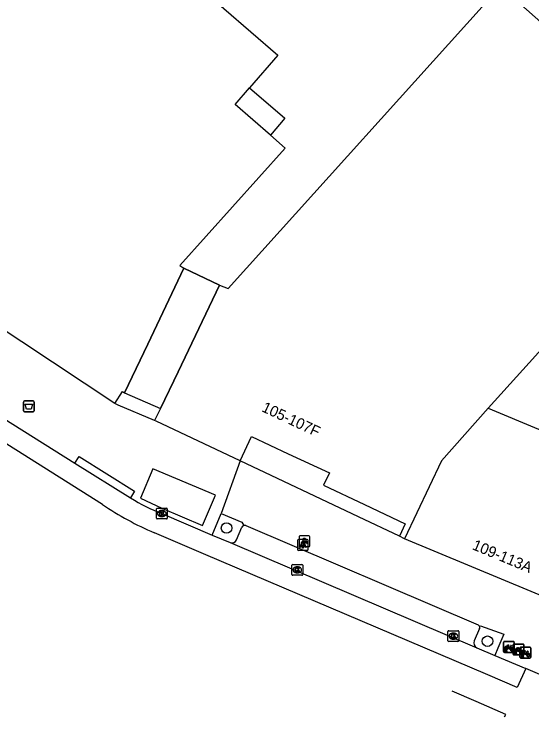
# Model space of a CAD drawing. Extents: x 161771 to 163125, y 382479 to 383177.
# Drawn here: x 162145.8 to 162193.7, y 382638.5 to 382703.5 of the extents above; entities that cross this region are included whole.
import ezdxf

# ---------------------------------------------------------------- set-up
doc = ezdxf.new("R2010")
doc.units = 0
for name, color, linetype in [('IMGEO_Afvalbak', 7, 'Continuous'), ('IMGEO_Boom', 7, 'Continuous'), ('IMGEO_Fietsenrek', 7, 'Continuous'), ('IMGEO_Kolk', 7, 'Continuous'), ('IMGEO_Lichtpunt', 7, 'Continuous'), ('IMGEO_Pand', 7, 'Continuous'), ('IMGEO_Pand_nummerreeks', 7, 'Continuous'), ('IMGEO_Pand_overbouw', 7, 'Continuous'), ('IMGEO_Parkeervlak_open', 7, 'Continuous'), ('IMGEO_Rijbaan_lokaal_gesloten', 7, 'Continuous'), ('IMGEO_Rijbaan_lokaal_open', 7, 'Continuous'), ('IMGEO_Voetpad_open', 7, 'Continuous')]:
    doc.layers.add(name, color=color, linetype=linetype)

msp = doc.modelspace()

# ---------------------------------------------------------------- linework, layer by layer
at = {"layer": 'IMGEO_Afvalbak'}
for p, q in [((162146.704, 382666.789), (162146.704, 382667.589)), ((162146.704, 382667.589), (162146.704, 382666.789)), ((162146.804, 382667.689), (162147.594, 382667.689)), ((162147.594, 382667.689), (162146.804, 382667.689)), ((162147.694, 382667.589), (162147.694, 382666.789)), ((162147.694, 382666.789), (162147.694, 382667.589)), ((162147.594, 382666.689), (162146.804, 382666.689)), ((162146.804, 382666.689), (162147.594, 382666.689))]:
    msp.add_line(p, q, dxfattribs=at)
msp.add_lwpolyline([(162146.847, 382667.403), (162147.551, 382667.403), (162147.402, 382666.933), (162146.996, 382666.933), (162146.847, 382667.403)], dxfattribs=at)
for centre, start, end in [((162146.804, 382667.589), 90, 180), ((162146.804, 382667.589), 90, 180), ((162147.594, 382667.589), 0, 90), ((162147.594, 382667.589), 360, 90), ((162146.804, 382666.789), 180, 270), ((162146.804, 382666.789), 180, 270), ((162147.594, 382666.789), 270, 0), ((162147.594, 382666.789), 270, 0)]:
    msp.add_arc(centre, 0.1, start, end, dxfattribs=at)
at = {"layer": 'IMGEO_Boom'}
for centre in [(162165.482, 382655.944), (162189.61, 382645.483)]:
    msp.add_circle(centre, 0.489, dxfattribs=at)
at = {"layer": 'IMGEO_Fietsenrek'}
for p, q in [((162191.09, 382644.528), (162191.09, 382645.369)), ((162191.09, 382645.369), (162191.09, 382644.528)), ((162191.165, 382645.453), (162192.006, 382645.453)), ((162192.006, 382645.453), (162191.165, 382645.453)), ((162192.052, 382645.218), (162192.893, 382645.218)), ((162192.893, 382645.218), (162192.052, 382645.218)), ((162192.09, 382645.378), (162192.09, 382644.537)), ((162192.09, 382644.537), (162192.09, 382645.378)), ((162191.217, 382644.537), (162191.256, 382644.697)), ((162191.251, 382644.537), (162191.217, 382644.537)), ((162191.286, 382644.685), (162191.251, 382644.537)), ((162191.328, 382644.709), (162191.327, 382644.713)), ((162191.369, 382644.537), (162191.335, 382644.679)), ((162191.359, 382644.72), (162191.36, 382644.713)), ((162191.367, 382644.683), (162191.402, 382644.537)), ((162191.402, 382644.537), (162191.369, 382644.537)), ((162191.777, 382645.002), (162191.813, 382644.907)), ((162191.977, 382644.293), (162191.977, 382645.134)), ((162191.977, 382645.134), (162191.977, 382644.293)), ((162192.613, 382644.004), (162192.613, 382644.845)), ((162192.613, 382644.845), (162192.613, 382644.004)), ((162192.664, 382644.767), (162192.7, 382644.672)), ((162192.688, 382644.929), (162193.529, 382644.929)), ((162193.529, 382644.929), (162192.688, 382644.929)), ((162192.977, 382645.143), (162192.977, 382644.302)), ((162192.977, 382644.302), (162192.977, 382645.143)), ((162193.613, 382644.854), (162193.613, 382644.013)), ((162193.613, 382644.013), (162193.613, 382644.854)), ((162192.015, 382644.453), (162191.174, 382644.453)), ((162191.174, 382644.453), (162192.015, 382644.453)), ((162192.902, 382644.218), (162192.061, 382644.218)), ((162192.061, 382644.218), (162192.902, 382644.218)), ((162192.104, 382644.302), (162192.143, 382644.462)), ((162192.138, 382644.302), (162192.104, 382644.302)), ((162192.173, 382644.45), (162192.138, 382644.302)), ((162192.215, 382644.474), (162192.214, 382644.478)), ((162192.256, 382644.302), (162192.222, 382644.444)), ((162192.246, 382644.485), (162192.247, 382644.478)), ((162192.254, 382644.448), (162192.289, 382644.302)), ((162192.289, 382644.302), (162192.256, 382644.302)), ((162193.538, 382643.929), (162192.697, 382643.929)), ((162192.697, 382643.929), (162193.538, 382643.929)), ((162192.74, 382644.013), (162192.779, 382644.173)), ((162192.774, 382644.013), (162192.74, 382644.013)), ((162192.809, 382644.161), (162192.774, 382644.013)), ((162192.851, 382644.185), (162192.85, 382644.189)), ((162192.892, 382644.013), (162192.858, 382644.155)), ((162192.882, 382644.196), (162192.883, 382644.189)), ((162192.89, 382644.159), (162192.925, 382644.013)), ((162192.925, 382644.013), (162192.892, 382644.013)), ((162193.3, 382644.478), (162193.336, 382644.383))]:
    msp.add_line(p, q, dxfattribs=at)
for points in [[(162191.424, 382644.927), (162191.372, 382644.837), (162191.332, 382644.812), (162191.333, 382644.859), (162191.388, 382644.953)], [(162191.403, 382644.979), (162191.498, 382645.143), (162191.584, 382645.129), (162191.586, 382645.12), (162191.53, 382645.109), (162191.503, 382645.064), (162191.759, 382645.023)], [(162191.699, 382644.735), (162191.649, 382644.735), (162191.458, 382644.986), (162191.439, 382644.954)], [(162191.746, 382644.998), (162191.489, 382645.039), (162191.472, 382645.01), (162191.639, 382644.79), (162191.746, 382644.998)], [(162191.794, 382644.9), (162191.764, 382644.977), (162191.655, 382644.759), (162191.698, 382644.759)], [(162191.728, 382644.759), (162191.848, 382644.758), (162191.804, 382644.872)], [(162191.824, 382644.879), (162191.879, 382644.734), (162191.729, 382644.734)], [(162191.759, 382645.023), (162191.784, 382645.072), (162191.778, 382645.076), (162191.755, 382645.08), (162191.743, 382645.087), (162191.742, 382645.09), (162191.744, 382645.095), (162191.839, 382645.08), (162191.841, 382645.07), (162191.831, 382645.057), (162191.819, 382645.051), (162191.805, 382645.057), (162191.777, 382645.002)], [(162192.311, 382644.692), (162192.259, 382644.602), (162192.219, 382644.577), (162192.22, 382644.624), (162192.275, 382644.718)], [(162192.29, 382644.744), (162192.385, 382644.908), (162192.471, 382644.894), (162192.473, 382644.885), (162192.417, 382644.874), (162192.39, 382644.829), (162192.646, 382644.788)], [(162192.586, 382644.5), (162192.536, 382644.5), (162192.345, 382644.751), (162192.326, 382644.719)], [(162192.633, 382644.763), (162192.376, 382644.804), (162192.359, 382644.775), (162192.526, 382644.555), (162192.633, 382644.763)], [(162192.681, 382644.665), (162192.651, 382644.742), (162192.542, 382644.524), (162192.585, 382644.524)], [(162192.615, 382644.524), (162192.735, 382644.523), (162192.691, 382644.637)], [(162192.711, 382644.644), (162192.766, 382644.499), (162192.616, 382644.499)], [(162192.646, 382644.788), (162192.671, 382644.837), (162192.665, 382644.841), (162192.642, 382644.845), (162192.63, 382644.852), (162192.629, 382644.855), (162192.631, 382644.86), (162192.726, 382644.845), (162192.728, 382644.835), (162192.718, 382644.822), (162192.706, 382644.816), (162192.692, 382644.822), (162192.664, 382644.767)], [(162192.926, 382644.455), (162193.021, 382644.619), (162193.107, 382644.605), (162193.109, 382644.596), (162193.053, 382644.585), (162193.026, 382644.54), (162193.282, 382644.499)], [(162193.269, 382644.474), (162193.012, 382644.515), (162192.995, 382644.486), (162193.162, 382644.266), (162193.269, 382644.474)], [(162193.282, 382644.499), (162193.307, 382644.548), (162193.301, 382644.552), (162193.278, 382644.556), (162193.266, 382644.563), (162193.265, 382644.566), (162193.267, 382644.571), (162193.362, 382644.556), (162193.364, 382644.546), (162193.354, 382644.533), (162193.342, 382644.527), (162193.328, 382644.533), (162193.3, 382644.478)], [(162192.947, 382644.403), (162192.895, 382644.313), (162192.855, 382644.288), (162192.856, 382644.335), (162192.911, 382644.429)], [(162193.222, 382644.211), (162193.172, 382644.211), (162192.981, 382644.462), (162192.962, 382644.43)], [(162193.317, 382644.376), (162193.287, 382644.453), (162193.178, 382644.235), (162193.221, 382644.235)], [(162193.251, 382644.235), (162193.371, 382644.234), (162193.327, 382644.348)], [(162193.347, 382644.355), (162193.402, 382644.21), (162193.252, 382644.21)]]:
    msp.add_lwpolyline(points, dxfattribs=at)
for centre, radius, start, end in [((162191.168, 382645.375), 0.0779, 92.4484, 184.28452), ((162191.168, 382645.375), 0.0779, 92.4484, 184.28452), ((162192.055, 382645.14), 0.0779, 92.4484, 184.28452), ((162192.055, 382645.14), 0.0779, 92.4484, 184.28452), ((162192.012, 382645.375), 0.0779, 2.4484, 94.28452), ((162192.012, 382645.375), 0.0779, 2.4484, 94.28452), ((162192.899, 382645.14), 0.0779, 2.4484, 94.28452), ((162192.899, 382645.14), 0.0779, 2.4484, 94.28452), ((162191.168, 382644.531), 0.0779, 182.4484, 274.28452), ((162191.168, 382644.531), 0.0779, 182.4484, 274.28452), ((162191.33, 382644.838), 0.159, 62.67661, 242.13685), ((162191.33, 382644.838), 0.129, 63.31916, 238.90302), ((162191.31, 382644.709), 0.0499, 12.8025, 158.69338), ((162191.33, 382644.838), 0.159, 253.99666, 271.78671), ((162191.31, 382644.709), 0.0174, 12.8025, 163.45023), ((162191.33, 382644.838), 0.129, 253.41502, 269.02044), ((162191.33, 382644.838), 0.129, 283.60429, 43.43025), ((162191.33, 382644.838), 0.159, 283.5766, 46.60424), ((162191.857, 382644.754), 0.159, 113.3408, 178.32165), ((162191.857, 382644.754), 0.159, 187.0065, 105.77075), ((162191.857, 382644.754), 0.129, 113.92302, 177.95563), ((162191.857, 382644.754), 0.129, 188.67146, 104.58832), ((162192.012, 382644.531), 0.0779, 272.4484, 4.28452), ((162192.012, 382644.531), 0.0779, 272.4484, 4.28452), ((162192.217, 382644.603), 0.159, 62.67661, 242.13685), ((162192.217, 382644.603), 0.129, 63.31916, 238.90302), ((162192.197, 382644.474), 0.0499, 12.8025, 158.69338), ((162192.217, 382644.603), 0.129, 283.60429, 43.43025), ((162192.217, 382644.603), 0.159, 283.5766, 46.60424), ((162192.744, 382644.519), 0.159, 113.3408, 178.32165), ((162192.744, 382644.519), 0.159, 187.0065, 105.77075), ((162192.691, 382644.851), 0.0779, 92.4484, 184.28452), ((162192.691, 382644.851), 0.0779, 92.4484, 184.28452), ((162192.744, 382644.519), 0.129, 113.92302, 177.95563), ((162192.744, 382644.519), 0.129, 188.67146, 104.58832), ((162193.535, 382644.851), 0.0779, 2.4484, 94.28452), ((162193.535, 382644.851), 0.0779, 2.4484, 94.28452), ((162192.055, 382644.296), 0.0779, 182.4484, 274.28452), ((162192.055, 382644.296), 0.0779, 182.4484, 274.28452), ((162192.217, 382644.603), 0.159, 253.99666, 271.78671), ((162192.197, 382644.474), 0.0174, 12.8025, 163.45023), ((162192.217, 382644.603), 0.129, 253.41502, 269.02044), ((162192.691, 382644.007), 0.0779, 182.4484, 274.28452), ((162192.691, 382644.007), 0.0779, 182.4484, 274.28452), ((162192.853, 382644.314), 0.159, 62.67661, 242.13685), ((162192.853, 382644.314), 0.129, 63.31916, 238.90302), ((162192.833, 382644.185), 0.0499, 12.8025, 158.69338), ((162192.853, 382644.314), 0.159, 253.99666, 271.78671), ((162192.833, 382644.185), 0.0174, 12.8025, 163.45023), ((162192.853, 382644.314), 0.129, 253.41502, 269.02044), ((162192.853, 382644.314), 0.129, 283.60429, 43.43025), ((162192.853, 382644.314), 0.159, 283.5766, 46.60424), ((162192.899, 382644.296), 0.0779, 272.4484, 4.28452), ((162192.899, 382644.296), 0.0779, 272.4484, 4.28452), ((162193.38, 382644.23), 0.159, 113.3408, 178.32165), ((162193.38, 382644.23), 0.159, 187.0065, 105.77075), ((162193.38, 382644.23), 0.129, 113.92302, 177.95563), ((162193.38, 382644.23), 0.129, 188.67146, 104.58832), ((162193.535, 382644.007), 0.0779, 272.4484, 4.28452), ((162193.535, 382644.007), 0.0779, 272.4484, 4.28452)]:
    msp.add_arc(centre, radius, start, end, dxfattribs=at)
at = {"layer": 'IMGEO_Kolk'}
for p, q in [((162158.997, 382656.858), (162158.997, 382657.71)), ((162159.072, 382657.784), (162159.924, 382657.784)), ((162159.485, 382657.564), (162159.51, 382657.564)), ((162159.998, 382657.71), (162159.998, 382656.858)), ((162159.508, 382657.004), (162159.483, 382657.004)), ((162159.924, 382656.784), (162159.072, 382656.784)), ((162171.523, 382651.653), (162171.523, 382652.505)), ((162171.598, 382652.579), (162172.45, 382652.579)), ((162172.011, 382652.359), (162172.036, 382652.359)), ((162172.524, 382652.505), (162172.524, 382651.653)), ((162172.034, 382651.799), (162172.009, 382651.799)), ((162172.45, 382651.579), (162171.598, 382651.579)), ((162186.026, 382646.452), (162186.878, 382646.452)), ((162185.951, 382645.526), (162185.951, 382646.378)), ((162186.439, 382646.232), (162186.464, 382646.232)), ((162186.952, 382646.378), (162186.952, 382645.526)), ((162186.878, 382645.452), (162186.026, 382645.452)), ((162186.462, 382645.672), (162186.437, 382645.672))]:
    msp.add_line(p, q, dxfattribs=at)
for points in [[(162158.997, 382656.858), (162158.997, 382657.71)], [(162159.072, 382657.784), (162159.924, 382657.784)], [(162159.998, 382657.71), (162159.998, 382656.858)], [(162159.318, 382657.484), (162159.441, 382657.484), (162159.441, 382657.333), (162159.571, 382657.484), (162159.735, 382657.484), (162159.589, 382657.333), (162159.742, 382657.084), (162159.59, 382657.084), (162159.505, 382657.248), (162159.441, 382657.181), (162159.441, 382657.084), (162159.318, 382657.084), (162159.318, 382657.484)], [(162159.924, 382656.784), (162159.072, 382656.784)], [(162171.523, 382651.653), (162171.523, 382652.505)], [(162171.598, 382652.579), (162172.45, 382652.579)], [(162172.524, 382652.505), (162172.524, 382651.653)], [(162171.844, 382652.279), (162171.967, 382652.279), (162171.967, 382652.128), (162172.097, 382652.279), (162172.261, 382652.279), (162172.115, 382652.128), (162172.268, 382651.879), (162172.116, 382651.879), (162172.031, 382652.043), (162171.967, 382651.976), (162171.967, 382651.879), (162171.844, 382651.879), (162171.844, 382652.279)], [(162172.45, 382651.579), (162171.598, 382651.579)], [(162186.026, 382646.452), (162186.878, 382646.452)], [(162185.951, 382645.526), (162185.951, 382646.378)], [(162186.272, 382646.152), (162186.395, 382646.152), (162186.395, 382646.001), (162186.525, 382646.152), (162186.689, 382646.152), (162186.543, 382646.001), (162186.696, 382645.752), (162186.544, 382645.752), (162186.459, 382645.916), (162186.395, 382645.849), (162186.395, 382645.752), (162186.272, 382645.752), (162186.272, 382646.152)], [(162186.952, 382646.378), (162186.952, 382645.526)], [(162186.878, 382645.452), (162186.026, 382645.452)]]:
    msp.add_lwpolyline(points, dxfattribs=at)
for centre, start, end in [((162159.074, 382657.708), 91.55205, 178.44795), ((162159.074, 382657.708), 91.55205, 178.44795), ((162159.922, 382657.708), 1.55205, 88.44795), ((162159.922, 382657.708), 1.55205, 88.44795), ((162159.074, 382656.86), 181.55205, 268.44795), ((162159.074, 382656.86), 181.55205, 268.44795), ((162159.922, 382656.86), 271.55205, 358.44795), ((162159.922, 382656.86), 271.55205, 358.44795), ((162171.6, 382652.503), 91.55205, 178.44795), ((162171.6, 382652.503), 91.55205, 178.44795), ((162172.448, 382652.503), 1.55205, 88.44795), ((162172.448, 382652.503), 1.55205, 88.44795), ((162171.6, 382651.655), 181.55205, 268.44795), ((162171.6, 382651.655), 181.55205, 268.44795), ((162172.448, 382651.655), 271.55205, 358.44795), ((162172.448, 382651.655), 271.55205, 358.44795), ((162186.028, 382646.376), 91.55205, 178.44795), ((162186.028, 382646.376), 91.55205, 178.44795), ((162186.876, 382646.376), 1.55205, 88.44795), ((162186.876, 382646.376), 1.55205, 88.44795), ((162186.028, 382645.528), 181.55205, 268.44795), ((162186.028, 382645.528), 181.55205, 268.44795), ((162186.876, 382645.528), 271.55205, 358.44795), ((162186.876, 382645.528), 271.55205, 358.44795)]:
    msp.add_arc(centre, 0.0765, start, end, dxfattribs=at)
for centre, major_axis, ratio, start_param, end_param in [((162159.484, 382657.284), (-0.387, 0.002), 0.722429, 4.712389, 7.853982), ((162159.509, 382657.284), (-0.39, 0.002), 0.717154, 1.570796, 4.712389), ((162172.01, 382652.079), (-0.387, 0.002), 0.722429, 4.712389, 7.853982), ((162172.035, 382652.079), (-0.39, 0.002), 0.717154, 1.570796, 4.712389), ((162186.438, 382645.952), (-0.387, 0.002), 0.722429, 4.712389, 7.853982), ((162186.463, 382645.952), (-0.39, 0.002), 0.717154, 1.570796, 4.712389)]:
    msp.add_ellipse(centre, major_axis=major_axis, ratio=ratio, start_param=start_param, end_param=end_param, dxfattribs=at)
at = {"layer": 'IMGEO_Lichtpunt'}
for p, q in [((162172.183, 382655.125), (162172.183, 382654.318)), ((162172.183, 382655.125), (162172.183, 382654.318)), ((162173.085, 382655.22), (162172.277, 382655.22)), ((162173.085, 382655.22), (162172.277, 382655.22)), ((162173.179, 382654.318), (162173.179, 382655.125)), ((162173.179, 382654.318), (162173.179, 382655.125)), ((162172.04, 382654.785), (162172.04, 382653.978)), ((162172.04, 382654.785), (162172.04, 382653.978)), ((162172.942, 382654.88), (162172.134, 382654.88)), ((162172.942, 382654.88), (162172.134, 382654.88)), ((162173.036, 382653.978), (162173.036, 382654.785)), ((162173.036, 382653.978), (162173.036, 382654.785)), ((162172.134, 382653.884), (162172.942, 382653.884)), ((162172.134, 382653.884), (162172.942, 382653.884)), ((162172.277, 382654.224), (162173.085, 382654.224)), ((162172.277, 382654.224), (162173.085, 382654.224))]:
    msp.add_line(p, q, dxfattribs=at)
for points in [[(162172.414, 382654.449), (162172.453, 382654.421), (162172.265, 382654.159), (162172.227, 382654.186), (162172.414, 382654.449)], [(162172.557, 382654.789), (162172.596, 382654.761), (162172.408, 382654.499), (162172.37, 382654.526), (162172.557, 382654.789)], [(162172.516, 382654.401), (162172.563, 382654.401), (162172.563, 382654.079), (162172.516, 382654.079), (162172.516, 382654.401)], [(162172.626, 382654.421), (162172.664, 382654.448), (162172.851, 382654.186), (162172.812, 382654.158), (162172.626, 382654.421)], [(162172.659, 382654.741), (162172.706, 382654.741), (162172.706, 382654.419), (162172.659, 382654.419), (162172.659, 382654.741)], [(162172.769, 382654.761), (162172.807, 382654.788), (162172.994, 382654.526), (162172.955, 382654.498), (162172.769, 382654.761)]]:
    msp.add_lwpolyline(points, dxfattribs=at)
for centre in [(162172.682, 382654.923), (162172.539, 382654.583)]:
    msp.add_circle(centre, 0.0994, dxfattribs=at)
for centre, start, end in [((162172.277, 382655.125), 90, 180), ((162172.277, 382655.125), 90, 180), ((162173.085, 382655.125), 0, 90), ((162173.085, 382655.125), 0, 90), ((162172.134, 382654.785), 90, 180), ((162172.134, 382654.785), 90, 180), ((162172.277, 382654.318), 180, 270), ((162172.277, 382654.318), 180, 270), ((162172.942, 382654.785), 0, 90), ((162172.942, 382654.785), 0, 90), ((162173.085, 382654.318), 270, 0), ((162173.085, 382654.318), 270, 360), ((162172.134, 382653.978), 180, 270), ((162172.134, 382653.978), 180, 270), ((162172.942, 382653.978), 270, 0), ((162172.942, 382653.978), 270, 360)]:
    msp.add_arc(centre, 0.0946, start, end, dxfattribs=at)
at = {"layer": 'IMGEO_Pand'}
for points in [[(162131.52, 382700.111), (162142.065, 382716.037), (162148.795, 382710.213), (162152.742, 382714.774), (162170.21, 382699.659), (162167.606, 382696.65)], [(162164.832, 382678.395), (162165.639, 382678.074), (162190.797, 382706.034), (162209.762, 382689.239)], [(162169.537, 382692.264), (162166.263, 382695.098), (162167.606, 382696.65)], [(162169.537, 382692.264), (162170.916, 382691.071), (162161.176, 382680.213), (162161.532, 382679.977)], [(162209.762, 382689.239), (162189.675, 382667.014)], [(162155.142, 382667.451), (162123.641, 382688.309)], [(162156.045, 382668.44), (162158.193, 382672.956), (162161.532, 382679.977)], [(162164.832, 382678.395), (162160.996, 382670.394), (162159.369, 382667.001)], [(162155.142, 382667.451), (162155.872, 382668.555), (162156.045, 382668.44)], [(162159.369, 382667.001), (162158.834, 382665.885)], [(162189.675, 382667.014), (162185.346, 382662.156), (162181.94, 382654.954)], [(162189.675, 382667.014), (162198.614, 382663.288), (162204.11, 382660.982)], [(162166.726, 382662.151), (162158.988, 382665.812), (162158.834, 382665.885)], [(162166.726, 382662.151), (162167.795, 382664.411), (162171.191, 382662.819), (162174.993, 382661.036), (162174.459, 382659.906), (162178.229, 382658.124), (162182.008, 382656.338), (162181.461, 382655.181)], [(162181.94, 382654.954), (162181.461, 382655.181)], [(162199.862, 382647.487), (162181.94, 382654.954)]]:
    msp.add_lwpolyline(points, dxfattribs=at)
at = {"layer": 'IMGEO_Pand_overbouw'}
msp.add_lwpolyline([(162159.369, 382667.001), (162160.996, 382670.394), (162164.832, 382678.395), (162161.532, 382679.977), (162158.193, 382672.956), (162156.045, 382668.44)], close=True, dxfattribs=at)
at = {"layer": 'IMGEO_Parkeervlak_open'}
for points in [[(162166.395, 382654.863), (162166.886, 382656.019)], [(162188.884, 382646.65), (162188.387, 382645.503)]]:
    msp.add_lwpolyline(points, dxfattribs=at)
for centre, radius, start, end in [((162167.179, 382655.84), 0.343, 109.39282, 148.62599), ((162165.959, 382655.049), 0.474, 250.92438, 336.89261), ((162188.585, 382646.735), 0.311, 344.16047, 23.97216), ((162188.869, 382645.323), 0.514, 159.5046, 241.08835)]:
    msp.add_arc(centre, radius, start, end, dxfattribs=at)
at = {"layer": 'IMGEO_Rijbaan_lokaal_gesloten'}
for points in [[(162154.006, 382658.112), (162132.517, 382671.637), (162133.505, 382673.273)], [(162133.505, 382673.273), (162136.982, 382671.042), (162151.466, 382661.952)], [(162151.466, 382661.952), (162156.611, 382658.724)], [(162159.498, 382657.284), (162164.159, 382655.281)], [(162193.15, 382642.947), (162192.365, 382641.208), (162189.65, 382642.363), (162163.357, 382653.575), (162158.806, 382655.504)], [(162164.159, 382655.281), (162165.804, 382654.601)], [(162165.804, 382654.601), (162188.62, 382644.873)], [(162188.62, 382644.873), (162190.279, 382644.168)], [(162190.279, 382644.168), (162193.15, 382642.947)], [(162191.188, 382638.482), (162191.293, 382638.722), (162188.567, 382639.907), (162186.349, 382640.853)]]:
    msp.add_lwpolyline(points, dxfattribs=at)
for centre, radius, start, end in [((162165.614, 382673.159), 17.013, 238.04967, 248.93142), ((162170.594, 382682.92), 29.843, 236.23199, 246.7346)]:
    msp.add_arc(centre, radius, start, end, dxfattribs=at)
at = {"layer": 'IMGEO_Rijbaan_lokaal_open'}
for points in [[(162161.532, 382679.977), (162164.832, 382678.395)], [(162156.045, 382668.44), (162159.369, 382667.001)], [(162158.834, 382665.885), (162155.47, 382667.312), (162155.142, 382667.451)], [(162198.856, 382640.517), (162193.15, 382642.947)]]:
    msp.add_lwpolyline(points, dxfattribs=at)
at = {"layer": 'IMGEO_Voetpad_open'}
for points in [[(162167.606, 382696.65), (162170.881, 382693.817), (162169.537, 382692.264)], [(162151.466, 382661.952), (162151.842, 382662.545), (162156.972, 382659.358), (162156.611, 382658.724)], [(162166.726, 382662.151), (162164.994, 382657.286)], [(162181.461, 382655.181), (162177.682, 382656.968), (162166.726, 382662.151)], [(162158.673, 382661.422), (162157.511, 382658.717), (162159.498, 382657.778), (162163.271, 382656.17), (162164.452, 382658.97), (162158.673, 382661.422)], [(162164.159, 382655.281), (162164.994, 382657.286)], [(162164.994, 382657.286), (162166.905, 382656.487), (162167.065, 382656.164)], [(162167.258, 382656.173), (162188.739, 382647.005)], [(162188.869, 382646.861), (162188.97, 382646.896), (162191.117, 382646.135), (162190.568, 382644.845), (162190.279, 382644.168)]]:
    msp.add_lwpolyline(points, dxfattribs=at)
for centre, radius, start, end in [((162167.176, 382655.854), 0.329, 75.58879, 109.75099), ((162188.586, 382646.736), 0.309, 23.79212, 60.35792)]:
    msp.add_arc(centre, radius, start, end, dxfattribs=at)

# ---------------------------------------------------------------- texts
at = {"layer": 'IMGEO_Pand_nummerreeks'}
for s, rotation, p in [('105-107F', 334.86705, (162168.655, 382666.762)), ('109-113A', 337.37963, (162188.126, 382654.002))]:
    msp.add_text(s, height=1, rotation=rotation, dxfattribs=at).set_placement(p)

doc.saveas('drawing.dxf')
